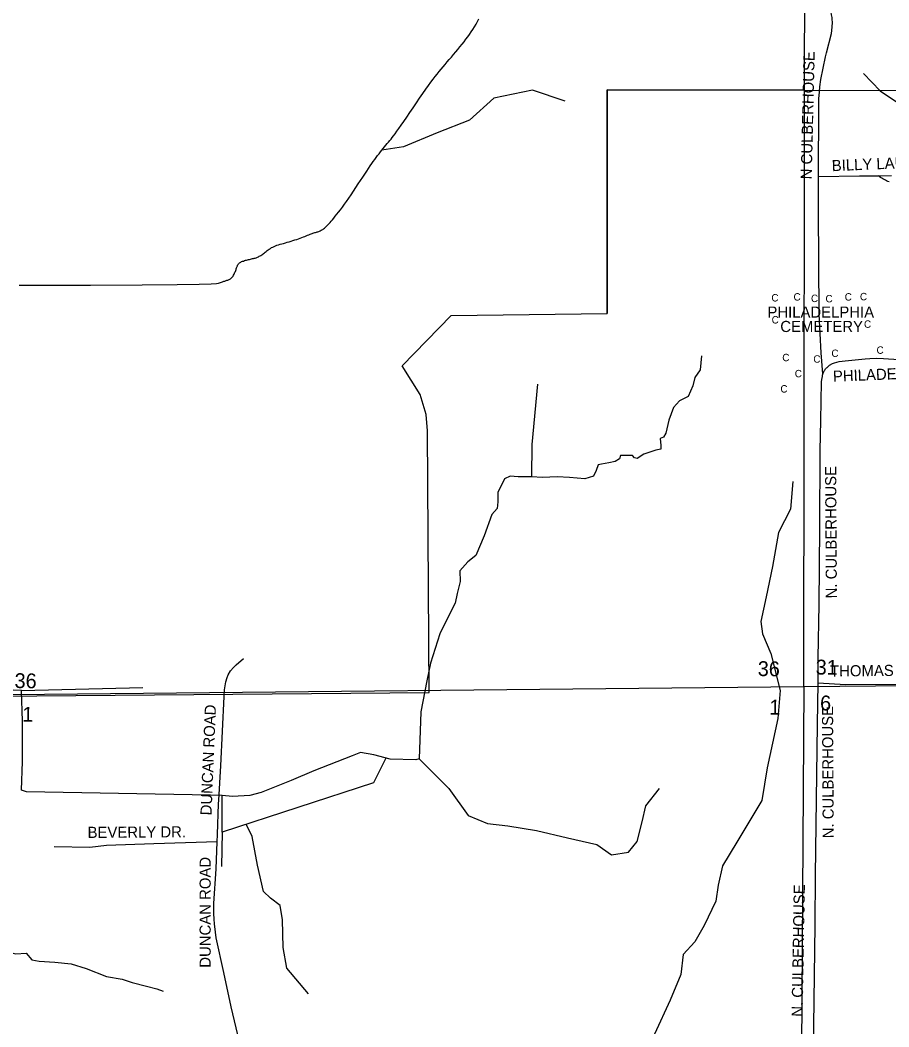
# Model space of a CAD drawing. Extents: x 1670563 to 1761545, y 515755 to 578944.
# Drawn here: x 1688618 to 1694474, y 562863 to 569646 of the extents above; entities that cross this region are included whole.
import ezdxf

# ---------------------------------------------------------------- set-up
doc = ezdxf.new("R2010")
doc.units = 0
for name, color, linetype in [('4_TwnRge', 7, 'Continuous'), ('62_text', 7, 'Continuous'), ('CEMETERY', 7, 'Continuous'), ('Cross', 7, 'Continuous'), ('LIMITS', 7, 'Continuous'), ('SHP_LINE', 7, 'Continuous'), ('STREETCL', 7, 'Continuous'), ('STRNAMES', 7, 'Continuous')]:
    doc.layers.add(name, color=color, linetype=linetype)

# ---------------------------------------------------------------- blocks, each defined once
blk = doc.blocks.new('CITY_LIMITS02')
at = {"layer": 'LIMITS'}
for p, q in [((1692575.8, 569175.5), (1692574.3, 567670.1)), ((1693901.6, 569174.2), (1692575.8, 569175.5)), ((1691376.2, 565115.2), (1691364.1, 566879.4)), ((1686369.7, 565075.1), (1691376.2, 565115.2))]:
    blk.add_line(p, q, dxfattribs=at)
for points in [[(1691364.1, 566879.4), (1691355.5, 566989.8), (1691315.4, 567123.6), (1691192.5, 567317.1), (1691522.5, 567656), (1692574.3, 567670.1), (1692575.8, 569175.5)], [(1692575.8, 569175.5), (1693901.6, 569174.2)], [(1693901.6, 569174.2), (1699390.4, 569172.5)]]:
    blk.add_lwpolyline(points, dxfattribs=at)

msp = doc.modelspace()

# ---------------------------------------------------------------- linework, layer by layer
at = {"layer": '4_TwnRge'}
for points in [[(1693900.8, 565154.5), (1693907, 570442.1), (1693901.9, 570514.1), (1693918.7, 572370.1)], [(1720455.1, 565306), (1715208.3, 565227.8), (1715092.6, 565233.3), (1710001.7, 565251.4), (1709850.1, 565251.4), (1704696.7, 565228.3), (1704511, 565220.7), (1699397.7, 565205.1), (1699224.1, 565203.4), (1693900.8, 565154.5), (1688559.5, 565099.9), (1688483.7, 565104.9), (1683270, 565036.6)], [(1693900.8, 565154.5), (1693867.8, 559919.3), (1693819.4, 554617.2), (1693735.2, 549363.2), (1693687.1, 544103.2), (1693620.9, 538819.1), (1693684.6, 533590.9), (1693722.5, 528338.7), (1693732, 528106.5), (1693805.9, 522944.4), (1693926.3, 517684.2)]]:
    msp.add_lwpolyline(points, dxfattribs=at)
at = {"layer": 'SHP_LINE'}
for p, q in [((1691670, 569584), (1691681, 569601)), ((1691681, 569601), (1691691, 569619)), ((1691691, 569619), (1691701, 569637)), ((1691701, 569637), (1691711, 569654)), ((1691623, 569517), (1691636, 569533)), ((1691636, 569533), (1691648, 569550)), ((1691648, 569550), (1691659, 569567)), ((1691659, 569567), (1691670, 569584)), ((1691569, 569449), (1691583, 569466)), ((1691583, 569466), (1691597, 569483)), ((1691597, 569483), (1691610, 569500)), ((1691610, 569500), (1691623, 569517)), ((1691511, 569380), (1691525, 569397)), ((1691525, 569397), (1691540, 569415)), ((1691540, 569415), (1691555, 569432)), ((1691555, 569432), (1691569, 569449)), ((1691456, 569315), (1691469, 569331)), ((1691469, 569331), (1691482, 569347)), ((1691482, 569347), (1691496, 569364)), ((1691496, 569364), (1691511, 569380)), ((1691402, 569248), (1691416, 569266)), ((1691416, 569266), (1691430, 569283)), ((1691430, 569283), (1691443, 569299)), ((1691443, 569299), (1691456, 569315)), ((1691352, 569180), (1691370, 569205)), ((1691370, 569205), (1691387, 569228)), ((1691387, 569228), (1691402, 569248)), ((1691289, 569089), (1691311, 569121)), ((1691311, 569121), (1691333, 569152)), ((1691333, 569152), (1691352, 569180)), ((1691245, 569024), (1691267, 569056)), ((1691267, 569056), (1691289, 569089)), ((1691204, 568964), (1691224, 568993)), ((1691224, 568993), (1691245, 569024)), ((1691157, 568897), (1691171, 568916)), ((1691171, 568916), (1691186, 568938)), ((1691186, 568938), (1691204, 568964))]:
    msp.add_line(p, q, dxfattribs=at)
for points in [[(1694302, 569287), (1694416, 569170), (1694876, 568860), (1695053, 568653), (1695296, 568336), (1695500, 568230), (1695597, 568120), (1695665, 567957), (1695665, 567801), (1695782, 567771), (1695892, 567631), (1695865, 567328), (1695999, 567184), (1696222, 567151), (1696419, 567084), (1696547, 567019)], [(1692293, 569099), (1692072, 569174), (1691811, 569121), (1691648, 568971), (1691430, 568886), (1691202, 568793), (1691056, 568769)], [(1688612, 567861), (1689093, 567861), (1689441, 567862), (1689677, 567864), (1689825, 567866), (1689906, 567869), (1689941, 567872), (1689954, 567874), (1689962, 567877), (1689969, 567879), (1689975, 567881), (1689981, 567883), (1689987, 567885), (1689992, 567887), (1689997, 567888), (1690002, 567890), (1690007, 567891), (1690012, 567893), (1690017, 567894), (1690022, 567896), (1690027, 567898), (1690032, 567901), (1690036, 567904), (1690041, 567908), (1690045, 567912), (1690049, 567917), (1690053, 567922), (1690057, 567928), (1690060, 567934), (1690064, 567940), (1690066, 567947), (1690069, 567953), (1690071, 567959), (1690073, 567965), (1690075, 567970), (1690076, 567976), (1690078, 567981), (1690080, 567986), (1690082, 567991), (1690084, 567995), (1690087, 567999), (1690090, 568003), (1690093, 568007), (1690097, 568010), (1690101, 568013), (1690106, 568016), (1690111, 568019), (1690117, 568021), (1690123, 568023), (1690130, 568026), (1690136, 568028), (1690143, 568029), (1690150, 568031), (1690157, 568033), (1690164, 568034), (1690171, 568036), (1690178, 568037), (1690184, 568039), (1690190, 568040), (1690196, 568042), (1690202, 568043), (1690208, 568045), (1690214, 568047), (1690219, 568049), (1690225, 568052), (1690230, 568055), (1690236, 568058), (1690241, 568061), (1690247, 568065), (1690253, 568069), (1690258, 568073), (1690264, 568078), (1690270, 568082), (1690277, 568087), (1690283, 568093), (1690290, 568098), (1690297, 568103), (1690305, 568108), (1690313, 568113), (1690321, 568117), (1690330, 568121), (1690339, 568125), (1690349, 568129), (1690360, 568132), (1690371, 568136), (1690382, 568139), (1690394, 568142), (1690406, 568146), (1690418, 568149), (1690431, 568153), (1690444, 568157), (1690457, 568161), (1690470, 568165), (1690482, 568169), (1690494, 568173), (1690506, 568177), (1690517, 568181), (1690528, 568185), (1690538, 568189), (1690547, 568193), (1690556, 568197), (1690564, 568200), (1690572, 568203), (1690579, 568206), (1690586, 568208), (1690592, 568210), (1690598, 568212), (1690604, 568214), (1690609, 568215), (1690615, 568217), (1690620, 568219), (1690625, 568220), (1690631, 568222), (1690636, 568225), (1690641, 568227), (1690647, 568230), (1690652, 568233), (1690658, 568236), (1690663, 568240), (1690669, 568245), (1690675, 568249), (1690680, 568255), (1690686, 568261), (1690693, 568267), (1690699, 568274), (1690707, 568282), (1690715, 568292), (1690723, 568301), (1690732, 568312), (1690742, 568325), (1690753, 568338), (1690765, 568353), (1690777, 568368), (1690790, 568386), (1690804, 568405), (1690818, 568425), (1690833, 568447), (1690849, 568470), (1690865, 568494), (1690881, 568518), (1690897, 568542), (1690912, 568565), (1690927, 568588), (1690941, 568609), (1690954, 568629), (1690966, 568647), (1690977, 568664), (1690988, 568679), (1690998, 568694), (1691008, 568708), (1691018, 568721), (1691027, 568733), (1691037, 568746), (1691046, 568758), (1691056, 568769), (1691065, 568781), (1691075, 568792), (1691084, 568803), (1691093, 568814), (1691101, 568824), (1691109, 568834), (1691118, 568844), (1691126, 568855), (1691135, 568867), (1691146, 568881), (1691157, 568897)], [(1693210, 567383), (1693203, 567289), (1693166, 567238), (1693152, 567181), (1693122, 567109), (1693063, 567080), (1693022, 567036), (1692990, 566950), (1692971, 566862), (1692954, 566836), (1692933, 566828), (1692938, 566779), (1692938, 566756), (1692903, 566748), (1692823, 566722), (1692777, 566692), (1692760, 566697), (1692747, 566713), (1692707, 566713), (1692665, 566713), (1692659, 566690), (1692628, 566673), (1692587, 566664), (1692536, 566655), (1692514, 566650), (1692500, 566611), (1692482, 566573), (1692424, 566555), (1692322, 566564), (1692239, 566568), (1692139, 566564), (1692065, 566569)], [(1692106, 567193), (1692067, 566787), (1692065, 566569)], [(1692065, 566569), (1691976, 566569), (1691921, 566573), (1691884, 566555), (1691837, 566464), (1691839, 566401), (1691834, 566355), (1691797, 566316), (1691745, 566171), (1691689, 566038), (1691635, 565996), (1691582, 565936), (1691584, 565864), (1691563, 565782), (1691550, 565718), (1691519, 565657), (1691448, 565510), (1691385, 565313), (1691359, 565194), (1691319, 564986), (1691307, 564668), (1691286, 564661), (1691112, 564667), (1691003, 564695), (1690912, 564712), (1690857, 564689), (1690598, 564588), (1690445, 564522), (1690243, 564441), (1690166, 564422), (1690050, 564416), (1689979, 564422), (1689902, 564425), (1688660, 564446), (1688627, 564458), (1688634, 564650), (1688634, 564922), (1688627, 565130)], [(1693826, 566538), (1693810, 566350), (1693730, 566193), (1693690, 565965), (1693646, 565760), (1693610, 565595), (1693622, 565511), (1693678, 565379), (1693742, 565130), (1693726, 564941), (1693654, 564609), (1693618, 564388), (1693449, 564107), (1693352, 563947), (1693324, 563818), (1693308, 563710), (1693228, 563545), (1693167, 563436), (1693087, 563351), (1693071, 563215), (1692999, 563042), (1692894, 562814)], [(1688627, 565130), (1688287, 565143), (1688219, 565145)], [(1688627, 565130), (1689446, 565149)], [(1691084, 564674), (1691001, 564507), (1689980, 564175)], [(1691307, 564668), (1691508, 564469), (1691637, 564288), (1691768, 564232), (1691906, 564218), (1692099, 564186), (1692307, 564136), (1692505, 564092), (1692605, 564022), (1692719, 564039), (1692777, 564112), (1692812, 564244), (1692836, 564352), (1692929, 564469)], [(1689980, 564175), (1689979, 564422)], [(1689980, 564175), (1689976, 563944)], [(1690561, 563086), (1690416, 563258), (1690392, 563397), (1690386, 563584), (1690371, 563681), (1690305, 563729), (1690259, 563775), (1690217, 563953), (1690181, 564146), (1690142, 564228)], [(1687757, 563355), (1687865, 563383), (1687945, 563383), (1688097, 563381), (1688205, 563373), (1688419, 563381), (1688452, 563394), (1688534, 563368), (1688588, 563355), (1688658, 563360), (1688696, 563314), (1688745, 563306), (1688851, 563299), (1688961, 563288), (1689062, 563257), (1689199, 563203), (1689305, 563185), (1689374, 563162), (1689469, 563136), (1689539, 563118), (1689582, 563103)]]:
    msp.add_lwpolyline(points, dxfattribs=at)
at = {"layer": 'STREETCL'}
for points in [[(1694000.4, 568592.3), (1694003.1, 569070.5), (1694003.1, 569116.2), (1694005.7, 569163.2), (1694007.8, 569196.4), (1694015.1, 569247.1), (1694047.5, 569398.4), (1694053.6, 569426.5), (1694087.3, 569555.8), (1694090.5, 569575.9), (1694093.4, 569626.7), (1694093.3, 569636), (1694092.8, 569645.3), (1694092.1, 569654.6), (1694091.2, 569663.9), (1694089.9, 569673.2), (1694088.4, 569682.4), (1694084.8, 569700.4), (1694080.6, 569718.3), (1694075.8, 569736), (1694070.3, 569753.6), (1694010.5, 569935.8)], [(1694029.5, 567262.5), (1694018.8, 567404.7), (1694004.4, 567664.7), (1693999.1, 568362.4), (1694000.4, 568592.3)], [(1694000.4, 568592.3), (1694276.6, 568596.8), (1694400.8, 568598), (1694491.4, 568599)], [(1694476.6, 568556), (1694467.8, 568559.4), (1694459.1, 568563.2), (1694450.5, 568567.3), (1694442, 568571.6), (1694433.7, 568576.3), (1694425.6, 568581.2), (1694417.6, 568586.4), (1694409.8, 568591.9), (1694402.2, 568597.6)], [(1694029.5, 567262.5), (1694030.7, 567265.8), (1694031.9, 567269), (1694033.2, 567272.2), (1694034.7, 567275.4), (1694036.2, 567278.5), (1694037.9, 567281.5), (1694039.6, 567284.5), (1694041.5, 567287.5), (1694043.4, 567290.3), (1694045.5, 567293.1), (1694047.6, 567295.9), (1694049.9, 567298.5), (1694052.2, 567301.1), (1694054.6, 567303.6), (1694057.1, 567306), (1694059.7, 567308.3), (1694062.4, 567310.6), (1694073.9, 567321.1), (1694095.1, 567332.7), (1694107.6, 567337.5), (1694123.9, 567342.3), (1694138.3, 567345.1), (1694179.7, 567350.9), (1694315.2, 567364.4), (1694346, 567367.2), (1694390.2, 567368.2), (1694438.3, 567365.3), (1694540.2, 567358.6)], [(1693996.7, 565181.3), (1693997.2, 565239.8), (1693998.5, 565348.5), (1694003.5, 565709.2), (1694008.3, 566226), (1694011.2, 566745.8), (1694015.1, 566948.5), (1694020.9, 567208.8), (1694022.8, 567224.2), (1694025.7, 567245.3), (1694026.2, 567248.8), (1694026.9, 567252.3), (1694027.6, 567255.7), (1694028.5, 567259.1), (1694029.5, 567262.5)], [(1689947, 564108.8), (1689949.2, 564159.8), (1689955.4, 564366), (1689956.2, 564390.7), (1689970, 564622.5), (1689981.5, 564855.2), (1689992.5, 565087.9), (1689995.2, 565134.2), (1690004, 565188), (1690012.8, 565215.7), (1690020.3, 565235.1), (1690036.6, 565262), (1690055.2, 565283.2), (1690073.7, 565302.6), (1690123.3, 565344.3)], [(1693966.8, 562589.2), (1693967, 562644.4), (1693968.3, 562870.9), (1693972.8, 563209.3), (1693976.7, 563547.7), (1693978.6, 563884.2), (1693983.8, 564224.5), (1693988.9, 564563.6), (1693994, 564900.7), (1693996.7, 565181.3)], [(1693996.7, 565181.3), (1694182.1, 565170.3), (1694585, 565171), (1695251.5, 565178.1), (1695449.8, 565180.2)], [(1689947, 564108.8), (1689520.2, 564096.1), (1689199.8, 564084.2), (1689088, 564072.3), (1688848, 564076.5)], [(1690141, 562594), (1690114.8, 562682.6), (1690095.8, 562761.9), (1690041.4, 562996.8), (1689990.2, 563229.9), (1689939.9, 563462.2), (1689929.7, 563539.7), (1689927.9, 563555.1), (1689925.7, 563591.7), (1689924.4, 563624.3), (1689924.4, 563694), (1689939.4, 563927.1), (1689947, 564108.8)]]:
    msp.add_lwpolyline(points, dxfattribs=at)

# ---------------------------------------------------------------- block references
msp.add_blockref('CITY_LIMITS02', (0, 0), dxfattribs=at)

# ---------------------------------------------------------------- texts
at = {"layer": '62_text'}
for s, rotation, p in [('36', 358.92755, (1693589.5, 565227)), ('31', 358.92755, (1693980.1, 565237.5)), ('36', 358.92757, (1688579.5, 565146.2)), ('1', 358.92757, (1693667.3, 564967.5)), ('6', 358.92757, (1694009.7, 564995.6)), ('1', 358.9276, (1688631.7, 564919.6))]:
    msp.add_text(s, height=100, rotation=rotation, dxfattribs=at).set_placement(p)
at = {"layer": 'CEMETERY'}
for s, p in [('PHILADELPHIA', (1693655.5, 567641.4)), ('CEMETERY', (1693742.2, 567544.5))]:
    msp.add_text(s, height=75, dxfattribs=at).set_placement(p)
at = {"layer": 'Cross'}
for p in [(1693682, 567750.3), (1693831.3, 567756.3), (1693949, 567746.3), (1694046.7, 567744.3), (1694176.4, 567756.3), (1694279, 567758.2), (1693683.8, 567602), (1694306.3, 567573), (1694086.6, 567376.3), (1694391, 567397.7), (1693755.5, 567347.7), (1693964.9, 567337.8), (1693839.7, 567239.4), (1693742.9, 567136.6)]:
    msp.add_text('C', height=50, dxfattribs=at).set_placement(p)
at = {"layer": 'STRNAMES'}
for s, rotation, p in [('N CULBERHOUSE ', 88.65458, (1693954.1, 568572.6)), ('BILLY LANE', 2.45141, (1694090.7, 568627.8)), ('PHILADELPHIA RD.', 2.40149, (1694098.7, 567208.8)), ('N. CULBERHOUSE', 90.3273, (1694124.1, 565750)), ('THOMAS GREEN RD', 0.59263, (1694078.3, 565223)), ('DUNCAN ROAD', 87.6353, (1689907.6, 564286.6)), ('N. CULBERHOUSE', 90.3273, (1694103, 564133.5)), ('BEVERLY DR.', 0.36051, (1689072.7, 564135.6)), ('DUNCAN ROAD', 90, (1689902.5, 563261.2)), ('N. CULBERHOUSE  ', 88.99413, (1693892.6, 562930.3))]:
    msp.add_text(s, height=75, rotation=rotation, dxfattribs=at).set_placement(p)

doc.saveas('drawing.dxf')
